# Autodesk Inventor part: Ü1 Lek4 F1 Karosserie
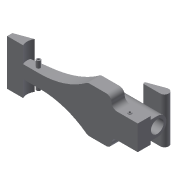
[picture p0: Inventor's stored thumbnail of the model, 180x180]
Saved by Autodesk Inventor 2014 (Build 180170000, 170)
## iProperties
Created: 2013-07
Part Number: Ü1 Lek4 F1 Karosserie
Material: Generisch
Document SubType Name: Modeling
Designer: Sofia
Density: 1 g/cm^3
Appearance: Vorgabe
Author: Sofia
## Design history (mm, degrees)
sketch "Skizze1"
  geometry: L1 (0, 0)-(200, 0); L2 (200, 0)-(200, 20); L3 (200, 20)-(110, 20); L4 (0, 8)-(0, 0); A1 r 510.167 centre (110, -490.167) between (110, 20) and (0, 8)
  constraints: 8 end point, 2 perpendicular, 2 point on circle, 1 centre point, 1 horizontal, 1 parallel, 1 tangent
  dimensions: "d2" = 200 distance of L1.start L1.end; "d3" = 20 distance of L1.end L2.end; "d4" = 90 distance of L2.end L3.end; "d5" = 8 distance of L4.start L1.start
extrude "Extrusion1" new body sketch "Skizze1" distance "d6" = 35; taper "d7" = 0 deg
sketch "Skizze2"
  geometry: L1 (0, 0)-(200, 0) reference; L2 (0, 35)-(200, 35) reference; L3 (0, 0)-(0, 35) reference; L4 (0, 10)-(50, 10); L5 (200, 35)-(160, 35); L6 (160, 35)-(160, 19); L7 (160, 19)-(200, 19); L8 (200, 19)-(200, 35); A1 r 120 centre (50, 130) between (50, 10) and (123.314, 35)
  constraints: 10 end point, 2 parallel, 2 perpendicular, 2 point on circle, 2 point on line, 1 centre point, 1 horizontal, 1 tangent
  dimensions: "d8" = 50 distance of L4.start L4.end; "d9" = 10 distance between parallel lines of L4 L1; "d10" = 120 radius of A1; "d13" = 40 distance of L7.end L6.end; "d14" = 16 distance of L6.end L5.end
extrude "Extrusion2" cut sketch "Skizze2" stored distance "d15" = 35; taper "d16" = 0 deg
sketch "Skizze3"
  geometry: L1 (0, 0)-(0, 8) reference; L2 (50, 0)-(0, 0) reference; C1 r 3 at (40, 8)
  constraints: 1 centre point
  dimensions: "d17" = 6 diameter of C1; "d18" = 8 distance from line of C1.centre L2; "d19" = 40 distance from line of C1.centre L1
extrude "Extrusion3" join sketch "Skizze3" distance "d20" = 10; taper "d21" = 0 deg
hole "Bohrung1" diameter "d24" = 3; stored, may be unused: countersink angle "d28" = 90 deg, drill point angle "d30" = 118 deg; dims "d22" = 10, "d23" = 10, "d25" = 6, "d26" = 4, "d27" = 2, "d29" = 8
pattern_linear "Rechteckige Anordnung1"
fillet "Rundung1" dims "d34" = 8
mirror "Spiegeln1"
sketch "Skizze4"
  geometry: L1 (38, 0)-(0, 0) reference; L2 (38, 20)-(0, 20) reference; L3 (5, 20)-(5, 30); L4 (33, 30)-(33, 20); A1 r 14 centre (19, 30) between (33, 30) and (5, 30); 2 further points
  constraints: 4 end point, 2 perpendicular, 2 point on circle, 2 point on line, 2 tangent, 1 centre point, 1 midpoint, 1 vertical alignment
  dimensions: "d35" = 14 radius of A1; "d36" = 30 distance from line of A1.centre L1
extrude "Extrusion4" join sketch "Skizze4" distance "d37" = 80; taper "d38" = 0 deg
sketch "Skizze5"
  geometry: L1 (200, 0)-(0, 0) reference; L2 (0, 0)-(0, 8) reference; L3 (110, 20)-(120, 20) reference; L4 (120, 20)-(120, 44) reference; L5 (120, 44)-(200, 44) reference; L6 (200, 44)-(200, 0) reference; L7 (25.066, 17.123)-(0, 8); L8 (168.592, 41)-(193.592, 41); L9 (191.4, 53.43)-(167.908, 44.879); C1 r 1.5 at (180, 8) reference; C2 r 1.5 at (40, 8) reference; A1 r 510.167 centre (110, -490.167) between (110, 20) and (0, 8) reference; A2 r 17.5 centre (40, 8) between (25.066, 17.123) and (24.436, 0); A3 r 6.408 centre (193.592, 47.408) between (193.592, 41) and (191.4, 53.43); A4 r 2 centre (168.592, 43) between (167.908, 44.879) and (168.592, 41)
  constraints: 6 end point, 6 point on circle, 5 tangent, 3 centre point, 1 coincident, 1 perpendicular, 1 point on line
  dimensions: "d39" = 17.5 radius of A2; "d40" = 20 deg angle of L1 L7; "d41" = 20 deg angle of L8 L9; "d42" = 2 radius of A4; "d43" = 25 distance of L8.start L8.end; "d44" = 3 distance between parallel lines of L5 L8
  node "Schnittkanten projizieren1"
extrude "Extrusion5" join sketch "Skizze5" stored distance "d45" = 70; taper "d46" = 0 deg
extrude "Extrusion6" join sketch "Skizze5" stored distance "d47" = 70; taper "d48" = 0 deg
hole "Bohrung2" diameter "d51" = 19.5; stored, may be unused: countersink angle "d55" = 90 deg, drill point angle "d57" = 118 deg; dims "d49" = 10, "d50" = 10, "d52" = 6, "d53" = 4, "d54" = 2, "d56" = 55
node "Volumenkörper1"
